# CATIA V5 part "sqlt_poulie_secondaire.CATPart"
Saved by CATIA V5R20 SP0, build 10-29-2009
Part number: sqlt_poulie_secondaire
Publications: "rayon_poulie_secondaire", "hauteur_poulie_secondaire", "hauteur_pivot_pale", "rayon_pivot_pale-rayon_support", "Plan.1", "Point.1", "Droite.1", "Plan.2", "Point.2", "Point.3", "Point.5", "Point.6", "Point.7", "Point.8", "Point.9", "Point.10", "Point.11"
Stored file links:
  D:\ecole\thinkmotion\sqlt_poulie_secondaire.CATPart
  D:\ecole\thinkmotion\sqlt_eolienne.CATProduct
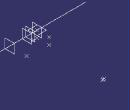
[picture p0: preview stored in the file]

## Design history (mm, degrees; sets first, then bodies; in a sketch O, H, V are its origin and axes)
Parameters
  rayon_poulie_secondaire = 200 mm {= External.rayon_poulie_secondaire}
  hauteur_poulie_secondaire = 10 mm {= External.hauteur_poulie_secondaire}
  hauteur_pivot_pale = 50 mm {= External.hauteur_pivot_pale}
  `rayon_pivot_pale-rayon_barre` = 30 mm {= External.rayon_pivot_pale -External.rayon_barre}
External parameters (linked from other documents)
  `External.diamètre_trou` = 40 mm
  External.rayon_pivot_soutient = 15 mm
  External.hauteur_pivot_soutient = 20 mm
  External.largeur_rainure = 3 mm
  External.hauteur_poulie = 10 mm
  External.profondeur_rainure = 1 mm
  External.hauteur_poulie_secondaire = 10 mm
  External.rayon_poulie_secondaire = 200 mm
  External.hauteur_pivot_pale = 50 mm
  External.rayon_pivot_pale = 50 mm
  External.rayon_barre = 20 mm
Set1 "poulie_secondaire"
  Plane1: type Offset, RefPlane xy-plane, Offset 0
  Point1: (0, 0, 0)
  Line1: type PtDir, RefPoint Point1, Direction yz-plane, Start 0, End 20
  Plane2: type Offset, RefPlane yz-plane, Offset 0
  Point2: (20 {= External.hauteur_pivot_soutient}, 55 {= `External.diamètre_trou` /2+External.rayon_pivot_soutient  +20mm}, 0)
  Point3: (20 {= External.hauteur_pivot_soutient}, 20 {= `External.diamètre_trou` /2}, 0)
  Point4: (30 {= External.hauteur_pivot_soutient +hauteur_poulie_secondaire}, 220 {= rayon_poulie_secondaire +`External.diamètre_trou` /2}, 0)
  Point5: (26.5 {= External.hauteur_pivot_soutient +hauteur_poulie_secondaire /2+External.largeur_rainure /2}, 220 {= `External.diamètre_trou` /2+rayon_poulie_secondaire}, 0)
  Point6: (23.5 {= hauteur_poulie_secondaire/2 +External.hauteur_pivot_soutient -External.largeur_rainure /2}, 219 {= `External.diamètre_trou` /2+rayon_poulie_secondaire -External.profondeur_rainure}, 0)
  Point7: (30 {= hauteur_poulie_secondaire +External.hauteur_pivot_soutient}, 20 {= `External.diamètre_trou` /2}, 0)
  Point8: (80 {= hauteur_poulie_secondaire +External.hauteur_pivot_soutient +hauteur_pivot_pale}, 50 {= `rayon_pivot_pale-rayon_barre` +`External.diamètre_trou` /2}, 0)
  Plane3: type Offset, RefPlane yz-plane, Offset 80 {= hauteur_pivot_pale  +hauteur_poulie_secondaire +External.hauteur_pivot_soutient}
  Plane4: type Offset, RefPlane Plane2, Offset 20 {= External.hauteur_pivot_soutient}
  Plane5: type Offset, RefPlane Plane4, Offset 10 {= hauteur_poulie_secondaire}
  Point9: (0, 35 {= `External.diamètre_trou` /2+External.rayon_pivot_soutient}, 0), relative to Point1
Body1 (main body)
